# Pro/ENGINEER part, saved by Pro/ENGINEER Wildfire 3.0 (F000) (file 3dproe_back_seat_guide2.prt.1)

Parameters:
  DESCRIPTION = "COMPRESSION NUT - 10"
  MODELED_BY = "L. CONARD"
  PTC_COMMON_NAME = "back_seat_guide2.prt"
